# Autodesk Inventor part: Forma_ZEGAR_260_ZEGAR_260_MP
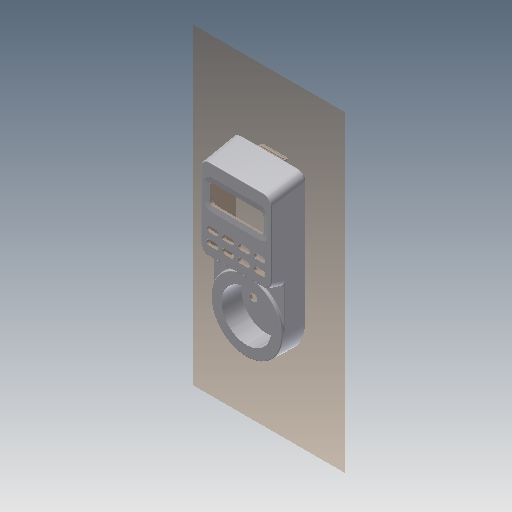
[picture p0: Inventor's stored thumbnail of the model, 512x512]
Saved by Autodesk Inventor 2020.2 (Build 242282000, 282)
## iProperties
Created: 2015-01
Part Number: Forma_ZEGAR_260_ZEGAR_260_MP
Material: Ogólny
Document SubType Name: Modeling
Designer: F.Stasiak
Density: 1 g/cm^3
Appearance: Domyślna
Catalog Web Link: www.expertbooks.pl
Manager: www.cadconsulting.pl
Company: Fabian Stasiak CAD Consulting
Author: F.Stasiak
Subject: Zbiór ćwiczeń. Autodesk Inventor 2020. Kurs Professional
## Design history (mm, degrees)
derived "ZEGAR_260.ipt"
node "Płaszczyzna konstrukcyjna1"
node "Płaszczyzna konstrukcyjna2"
node "Forma_ZEGAR_260_ZEGAR_260_WP"
feature "Zamknij obwiednię51" dims "d302" = 5, "d303" = 5, "d304" = 5, "d305" = 5, "d306" = 5, "d307" = 5, "d308" = 5, "d309" = 5, "d310" = 0
feature "Zamknij obwiednię52" dims "d311" = 5, "d312" = 5, "d313" = 5, "d314" = 5, "d315" = 0
feature "Zamknij obwiednię53" dims "d316" = 5, "d317" = 5, "d318" = 5, "d319" = 5, "d320" = 0
feature "Zamknij obwiednię54" dims "d321" = 5, "d322" = 5, "d323" = 5, "d324" = 5, "d325" = 0
feature "Zamknij obwiednię55" dims "d326" = 5, "d327" = 5, "d328" = 5, "d329" = 5, "d330" = 0
feature "Zamknij obwiednię56" dims "d331" = 5, "d332" = 5, "d333" = 5, "d334" = 5, "d335" = 0
feature "Zamknij obwiednię57" dims "d336" = 5, "d337" = 5, "d338" = 5, "d339" = 5, "d340" = 0
feature "Zamknij obwiednię58" dims "d341" = 5, "d342" = 5, "d343" = 5, "d344" = 5, "d345" = 0
feature "Zamknij obwiednię59" dims "d346" = 5, "d347" = 5, "d348" = 5, "d349" = 5, "d350" = 0
feature "Zamknij obwiednię60" dims "d351" = 5, "d352" = 0
feature "Zamknij obwiednię61" dims "d353" = 5, "d354" = 0
feature "Zamknij obwiednię62" dims "d355" = 5, "d356" = 0
node "Płaszczyzna konstrukcyjna5"
sketch "Szkic5"
  geometry: L1 (30.835, -178.031)-(30.835, 61.969); L2 (30.835, 61.969)-(-86.165, 61.969); L3 (-86.165, 61.969)-(-86.165, -178.031); L4 (-86.165, -178.031)-(30.835, -178.031); L5 (0, 0)-(0, -94.499) reference; L6 (-49.319, 6.101)-(-6.011, 6.101) reference; L7 (-55.33, -94.499)-(-55.33, 0) reference; A1 r 27.665 centre (-27.665, -94.499) between (-55.33, -94.499) and (0, -94.499) reference; 3 further points; 2 other entities
  constraints: 8 end point, 2 other
  dimensions: "d357" = 58.5 horizontal distance of point (-27.665, -58.031) L1.end (= 1.5 x Xmax); "d358" = 120 vertical distance of point (-27.665, -58.031) L1.end (= 1.5 x Ymax); "d359" = 58.5 horizontal distance of point (-27.665, -58.031) L2.end (= -1.5 x Xmin); "d360" = 120 vertical distance of point (-27.665, -58.031) L2.end (= 1.5 x Ymax); "d361" = 58.5 horizontal distance of point (-27.665, -58.031) L3.end (= -1.5 x Xmin); "d362" = 120 vertical distance of point (-27.665, -58.031) L3.end (= -1.5 x Ymin); "d363" = 58.5 horizontal distance of point (-27.665, -58.031) L1.start (= 1.5 x Xmax); "d364" = 120 vertical distance of point (-27.665, -58.031) L1.start (= -1.5 x Ymin)
feature "Zamknij obwiednię63" sketch "Szkic5"
feature "Oddzielenie matrycy5"
node "Płaszczyzna konstrukcyjna6"
sketch "Szkic6"
  geometry: L1 (0, -78)-(-20.191, -78) reference; L2 (-20.191, -78)-(-20.191, 0) reference; L3 (-17.791, -39)-(-12.991, -39); L4 (-17.791, -39)-(-15.391, -39); L5 (-17.791, -39)-(-17.791, -29.75); L6 (-20.191, -48.25)-(-15.391, -48.25); L7 (-15.391, -48.25)-(-15.391, -29.75); L8 (-15.391, -29.75)-(-20.191, -29.75); L9 (-20.191, -29.75)-(-20.191, -48.25)
  constraints: 14 end point, 1 horizontal, 1 perpendicular, 2 other
  dimensions: "d366" = 39 distance from line of L1 L3.start; "d367" = 2.4 distance from line of L2 L3.start; "d368" = 0 distance between parallel lines of L3 L4; "d369" = 4.8 distance between parallel lines of L9 L7; "d370" = 18.5 distance between parallel lines of L8 L6
extrude "Wyciągnięcie proste3" new body sketch "Szkic6" stored distance "d371" = 0.13; taper "d372" = 0 deg
node "Płaszczyzna konstrukcyjna7"
sketch "Szkic7"
  geometry: L1 (0, -18.5)-(-4.8, -18.5) reference; L2 (-4.8, -18.5)-(-4.8, 0) reference; L3 (-1.8, -9.25)-(4.2, -9.25); L4 (-1.8, -9.25)-(1.2, -9.25); L5 (-1.8, -9.25)-(-1.8, 5.75); L6 (-4.8, -24.25)-(1.2, -24.25); L7 (1.2, -24.25)-(1.2, 5.75); L8 (1.2, 5.75)-(-4.8, 5.75); L9 (-4.8, 5.75)-(-4.8, -24.25)
  constraints: 14 end point, 1 horizontal, 1 perpendicular, 2 other
  dimensions: "d374" = 9.25 distance from line of L1 L3.start; "d375" = 3 distance from line of L2 L3.start; "d376" = 0 distance between parallel lines of L3 L4; "d377" = 6 distance between parallel lines of L9 L7; "d378" = 30 distance between parallel lines of L8 L6
extrude "Wyciągnięcie proste4" join sketch "Szkic7" distance "d379" = 8; taper "d380" = 0 deg
feature "Bryła1::ZEGAR_260.ipt"
tag "Bryła wyprowadzona1"
feature "Bryła2::Forma_ZEGAR_260_ZEGAR_260_WP"
tag "Bryła wyprowadzona3"
body "Srf51"
body "Srf52"
body "Srf53"
body "Srf54"
body "Srf55"
body "Srf56"
body "Srf57"
body "Srf58"
body "Srf59"
body "Srf60"
body "Srf61"
body "Srf62"
body "Srf63"
node "Bryła13"
node "Bryła14"
node "Bryła15"
node "Bryła1"
feature "ZEGAR_260.ipt_Bodies"
node "Bryła12"
feature "Forma_ZEGAR_260_ZEGAR_260_WP_Bodies"
other parameters: "d8" = 39, "d9" = 39, "d13" = 0, "Xmin" = -39, "Xmax" = 39, "d365" = 0, "d373" = 0
